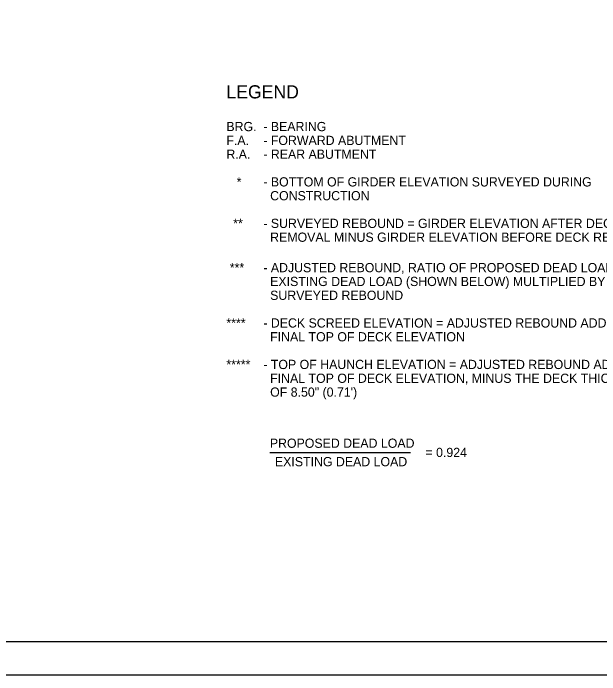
# Model space of a CAD drawing. Extents: x 0 to 34, y 0 to 22.
# Drawn here: x 20.39 to 29.29, y 0 to 10.04 of the extents above; entities that cross this region are included whole.
import ezdxf

# ---------------------------------------------------------------- set-up
doc = ezdxf.new("R2010")
doc.units = 0
for name, color, linetype in [('BR_P_Gen_Text', 7, 'Continuous'), ('SH_Border', 7, 'Continuous'), ('SH_Cut_Line', 7, 'Continuous')]:
    doc.layers.add(name, color=color, linetype=linetype)

msp = doc.modelspace()

# ---------------------------------------------------------------- linework, layer by layer
at = {"layer": 'BR_P_Gen_Text'}
msp.add_line((24.282, 3.376), (26.415, 3.376), dxfattribs=at)
at = {"layer": 'SH_Border'}
msp.add_lwpolyline([(1.5, 21.5), (33.5, 21.5), (33.5, 0.5), (1.5, 0.5)], close=True, dxfattribs=at)
at = {"layer": 'SH_Cut_Line'}
msp.add_lwpolyline([(0, 0), (34, 0), (34, 22), (0, 22)], close=True, dxfattribs=at)

# ---------------------------------------------------------------- texts
at = {"layer": 'BR_P_Gen_Text'}
for s, height, p in [('LEGEND', 0.2, (23.623, 8.751)), ('BRG.', 0.14, (23.623, 8.254)), ('- BEARING', 0.14, (24.183, 8.254)), ('F.A.', 0.14, (23.623, 8.044)), ('- FORWARD ABUTMENT', 0.14, (24.183, 8.044)), ('R.A.', 0.14, (23.623, 7.834)), ('- REAR ABUTMENT', 0.14, (24.183, 7.834)), ('   *', 0.14, (23.623, 7.414)), ('- BOTTOM OF GIRDER ELEVATION SURVEYED DURING ', 0.14, (24.183, 7.414)), ('  CONSTRUCTION', 0.14, (24.183, 7.204)), ('  **', 0.14, (23.623, 6.784)), ('- SURVEYED REBOUND = GIRDER ELEVATION AFTER DECK ', 0.14, (24.183, 6.784)), ('  REMOVAL MINUS GIRDER ELEVATION BEFORE DECK REMOVAL', 0.14, (24.183, 6.574)), (' ***', 0.14, (23.623, 6.112)), ('- ADJUSTED REBOUND, RATIO OF PROPOSED DEAD LOAD TO', 0.14, (24.183, 6.112)), ('  EXISTING DEAD LOAD (SHOWN BELOW) MULTIPLIED BY THE', 0.14, (24.183, 5.902)), ('  SURVEYED REBOUND', 0.14, (24.183, 5.692)), ('****', 0.14, (23.623, 5.272)), ('- DECK SCREED ELEVATION = ADJUSTED REBOUND ADDED TO THE', 0.14, (24.183, 5.272)), ('  FINAL TOP OF DECK ELEVATION', 0.14, (24.183, 5.062)), ('*****', 0.14, (23.623, 4.642)), ('- TOP OF HAUNCH ELEVATION = ADJUSTED REBOUND ADDED TO THE', 0.14, (24.183, 4.642)), ('  FINAL TOP OF DECK ELEVATION, MINUS THE DECK THICKNESS', 0.14, (24.183, 4.432)), ('  OF 8.50" (0.71\')', 0.14, (24.183, 4.222)), ('PROPOSED DEAD LOAD', 0.14, (24.282, 3.446)), ('= 0.924', 0.14, (26.643, 3.306)), ('EXISTING DEAD LOAD', 0.14, (24.359, 3.166))]:
    msp.add_text(s, height=height, dxfattribs=at).set_placement(p)

doc.saveas('drawing.dxf')
